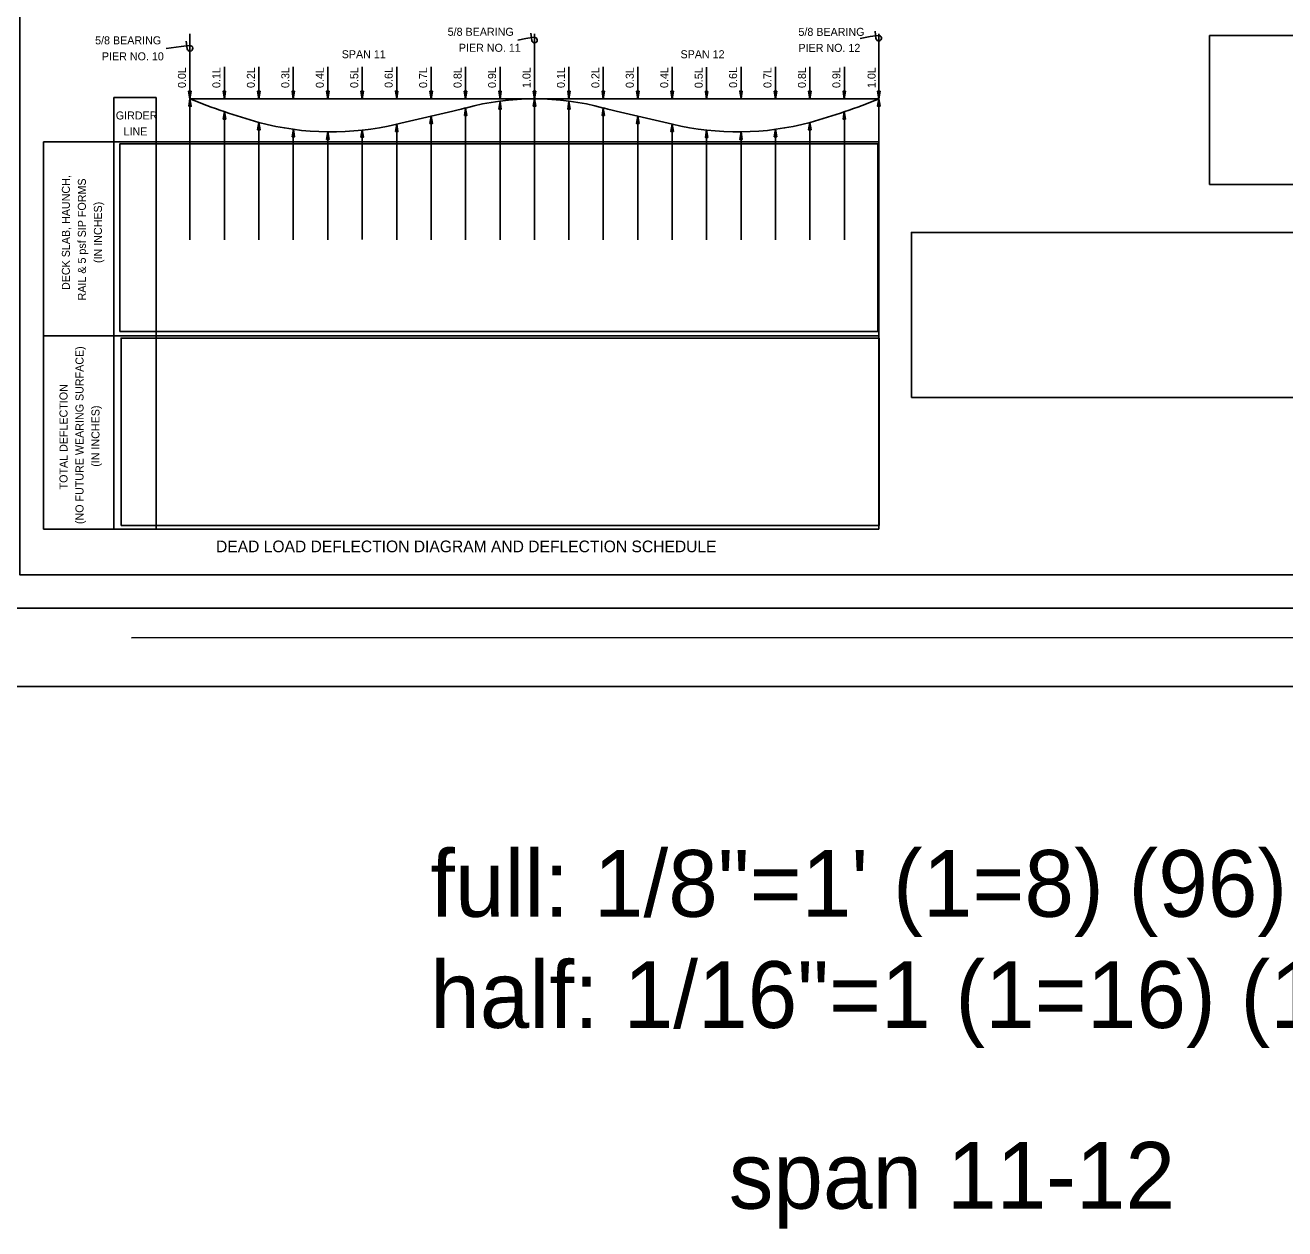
# Model space of a CAD drawing. Extents: x 4944 to 17449, y 3824 to 49087.
# Drawn here: x 7431 to 9244, y 35432 to 37164 of the extents above; entities that cross this region are included whole.
import ezdxf

# ---------------------------------------------------------------- set-up
doc = ezdxf.new("R2010")
doc.units = 0
for name, color, linetype in [('1', 7, 'Continuous'), ('37_S_TXT', 7, 'Continuous'), ('3A', 7, 'Continuous'), ('4', 7, 'Continuous'), ('6', 7, 'Continuous'), ('7', 7, 'Continuous'), ('BEAM', 7, 'Continuous'), ('DIM', 7, 'Continuous'), ('HATCH', 7, 'Continuous'), ('Level 14', 7, 'Continuous'), ('Level 25', 7, 'Continuous'), ('Level 34', 7, 'Continuous')]:
    doc.layers.add(name, color=color, linetype=linetype)

# ---------------------------------------------------------------- blocks, each defined once
blk = doc.blocks.new('DWG010')
at = {"layer": '1'}
for p, q in [((0, 0.047), (0.141, 0.047)), ((0.047, 0), (0.047, 0.125))]:
    blk.add_line(p, q, dxfattribs=at)
blk.add_arc((0, 0), 0.0469, 90, 0, dxfattribs=at)
blk = doc.blocks.new('ARROWH')
at = {"layer": '1'}
blk.add_lwpolyline([(0.123, -0.021), (0.123, 0.021), (-0.002, 0)], close=True, dxfattribs=at)

msp = doc.modelspace()

# ---------------------------------------------------------------- linework, layer by layer
at = {"layer": '37_S_TXT'}
msp.add_lwpolyline([(7079, 38515.9), (10535, 38515.9), (10535, 36211.9), (7079, 36211.9)], close=True, dxfattribs=at)
at = {"layer": '3A'}
for p, q in [((7668.1, 37151.1), (7668.1, 37057.9)), ((8163.9, 37151.1), (8163.9, 37057.9)), ((8659.4, 37151.1), (8659.4, 37057.9))]:
    msp.add_line(p, q, dxfattribs=at)
for points in [[(9135.4, 36934.3), (10068.7, 36934.3), (10068.7, 37148.9), (9135.4, 37148.9)], [(7567, 36723), (8657.9, 36723), (8657.9, 36992.8), (7567, 36992.8)], [(8706.4, 36627.8), (10414.2, 36627.8), (10414.2, 36865.5), (8706.4, 36865.5)], [(7569, 36443.7), (8659.8, 36443.7), (8659.8, 36713.5), (7569, 36713.5)]]:
    msp.add_lwpolyline(points, close=True, dxfattribs=at)
at = {"layer": '4'}
msp.add_line((7669.1, 36995.9), (8418.4, 36995.9), dxfattribs=at)
at = {"layer": '6'}
for p, q in [((8151.5, 37144.8), (8140, 37142.1)), ((8646.9, 37147.5), (8632.5, 37144.8)), ((7655.6, 37132.9), (7634, 37130.2)), ((7717.6, 37057.9), (7717.6, 37103.8)), ((7767.2, 37057.9), (7767.2, 37103.8)), ((7816.8, 37057.9), (7816.8, 37103.8)), ((7866.4, 37057.9), (7866.4, 37103.8)), ((7916, 37057.9), (7916, 37103.8)), ((7965.6, 37058.1), (7965.6, 37103.9)), ((8015.2, 37057.9), (8015.2, 37103.8)), ((8064.8, 37057.9), (8064.8, 37103.8)), ((8114.4, 37057.9), (8114.4, 37103.8)), ((8213.5, 37057.9), (8213.5, 37103.8)), ((8263, 37057.9), (8263, 37103.8)), ((8312.6, 37057.9), (8312.6, 37103.8)), ((8362.1, 37057.9), (8362.1, 37103.8)), ((8411.7, 37057.8), (8411.7, 37103.6)), ((8461.2, 37058.1), (8461.2, 37103.9)), ((8510.8, 37057.9), (8510.8, 37103.8)), ((8560.3, 37057.9), (8560.3, 37103.8)), ((8609.9, 37057.9), (8609.9, 37103.8)), ((7668.1, 36855.1), (7668.1, 37057.9)), ((7668.1, 37057.9), (7668.1, 37057.9)), ((7717.6, 37057.9), (7717.6, 37057.9)), ((7767.2, 37057.9), (7767.2, 37057.9)), ((7816.8, 37057.9), (7816.8, 37057.9)), ((7866.4, 37057.9), (7866.4, 37057.9)), ((7916, 37057.9), (7916, 37057.9)), ((7965.6, 37057.9), (7965.6, 37057.9)), ((8015.2, 37057.9), (8015.2, 37057.9)), ((8064.8, 37057.9), (8064.8, 37057.9)), ((8114.4, 37057.9), (8114.4, 37057.9)), ((8114.4, 36855.1), (8114.4, 37053.9)), ((8163.9, 36855.1), (8163.9, 37057.9)), ((8163.9, 37057.9), (8163.9, 37057.9)), ((8213.5, 37057.9), (8213.5, 37057.9)), ((8213.5, 36855.1), (8213.5, 37053.9)), ((8263, 37057.9), (8263, 37057.9)), ((8312.6, 37057.9), (8312.6, 37057.9)), ((8362.1, 37057.9), (8362.1, 37057.9)), ((8411.7, 37057.9), (8411.7, 37057.9)), ((8461.2, 37057.9), (8461.2, 37057.9)), ((8510.8, 37057.9), (8510.8, 37057.9)), ((8560.3, 37057.9), (8560.3, 37057.9)), ((8609.9, 37057.9), (8609.9, 37057.9)), ((8659.4, 36438.6), (8659.4, 37057.9)), ((8659.4, 37057.9), (8659.4, 37057.9)), ((7717.6, 36855.1), (7717.6, 37039.3)), ((8064.8, 36855.1), (8064.8, 37044.6)), ((8263, 36855.1), (8263, 37044.6)), ((8609.9, 36855.1), (8609.9, 37039.3)), ((7767.2, 36855.1), (7767.2, 37023.8)), ((7965.6, 36855.1), (7965.6, 37021.4)), ((8015.2, 36855.1), (8015.2, 37032.8)), ((8312.6, 36855.1), (8312.6, 37032.8)), ((8362.2, 36855.1), (8362.2, 37021.4)), ((8560.3, 36855.1), (8560.3, 37023.8)), ((7816.8, 36855.1), (7816.8, 37013.9)), ((7866.4, 36855.1), (7866.4, 37010.2)), ((7916, 36855.3), (7916, 37013.1)), ((8411.7, 36855.1), (8411.7, 37013)), ((8461.3, 36855.1), (8461.3, 37010.2)), ((8510.8, 36855.1), (8510.8, 37013.9))]:
    msp.add_line(p, q, dxfattribs=at)
at = {"layer": '7'}
for p, q in [((7668.1, 37057.9), (8163.9, 37057.9)), ((8163.9, 37057.9), (8659.4, 37057.9))]:
    msp.add_line(p, q, dxfattribs=at)
at = {"layer": 'BEAM'}
for centre, radius, start, end in [((8022.4, 37927.1), 938.7, 247.8233, 254.2284), ((8163.9, 36682.6), 375.3, 74.6834, 105.3166), ((8305.5, 37927.1), 938.7, 285.7716, 292.1767), ((6053.4, 45401.5), 8595.5, 282.85378, 283.53281), ((10274.5, 45401.5), 8595.5, 256.46719, 257.14622), ((7871.3, 37413.1), 402.9, 255.0329, 283.5345), ((8456.6, 37413.1), 402.9, 256.4655, 284.9671)]:
    msp.add_arc(centre, radius, start, end, dxfattribs=at)
at = {"layer": 'DIM'}
msp.add_lwpolyline([(7236.2, 38436.7), (10500.2, 38436.7), (10500.2, 36324.7), (7236.2, 36324.7)], close=True, dxfattribs=at)
at = {"layer": 'Level 14'}
msp.add_lwpolyline([(10447.4, 36372.7), (7423.4, 36372.7), (7423.4, 38388.7), (10447.4, 38388.7)], close=True, dxfattribs=at)
at = {"layer": 'Level 25'}
msp.add_line((7584.1, 36282.3), (10320.1, 36282.4), dxfattribs=at)
at = {"layer": 'Level 34'}
for p, q in [((7558.4, 36438.6), (7558.4, 37059.5)), ((7619.6, 37059.5), (7558.4, 37059.5)), ((7619.6, 36439.5), (7619.6, 37059.5)), ((7457.2, 36438.6), (7457.2, 36995.9)), ((8659.4, 36995.9), (7457.2, 36995.9)), ((7457.2, 36716.7), (8659.4, 36716.7)), ((7457.2, 36438.6), (8659.4, 36438.6))]:
    msp.add_line(p, q, dxfattribs=at)

# ---------------------------------------------------------------- block references
at = {"layer": '6'}
for name, p, xscale, yscale, rotation in [('DWG010', (8163.9, 37142.3), 85.92279574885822, -85.92279574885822, -172.86861111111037), ('DWG010', (8659.4, 37145), 85.92279574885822, -85.92279574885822, -172.8686111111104), ('DWG010', (7668.1, 37130.4), 85.92279574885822, -85.9227957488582, -172.86861111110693), ('ARROWH', (7668, 37058.1), 85.9227957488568, 85.9227957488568, 90), ('ARROWH', (7668.1, 37057.8), 85.92279574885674, 85.92279574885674, -90.00000000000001), ('ARROWH', (7717.6, 37058.1), 85.9227957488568, 85.9227957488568, 90), ('ARROWH', (7767.2, 37058.1), 85.9227957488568, 85.9227957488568, 90), ('ARROWH', (7816.8, 37058.1), 85.9227957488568, 85.9227957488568, 90), ('ARROWH', (7866.4, 37058.1), 85.9227957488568, 85.9227957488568, 90), ('ARROWH', (7916, 37058.1), 85.9227957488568, 85.9227957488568, 90), ('ARROWH', (7965.6, 37058.3), 85.9227957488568, 85.9227957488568, 90), ('ARROWH', (8015.2, 37058.1), 85.9227957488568, 85.9227957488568, 90), ('ARROWH', (8064.7, 37058.1), 85.9227957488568, 85.9227957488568, 90), ('ARROWH', (8114.3, 37058.1), 85.9227957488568, 85.9227957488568, 90), ('ARROWH', (8114.4, 37053.6), 85.92279574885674, 85.92279574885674, -90.00000000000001), ('ARROWH', (8163.9, 37058.1), 85.9227957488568, 85.9227957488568, 90), ('ARROWH', (8164, 37057.8), 85.92279574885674, 85.92279574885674, -90.00000000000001), ('ARROWH', (8213.5, 37058.1), 85.9227957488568, 85.9227957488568, 90), ('ARROWH', (8213.5, 37053.6), 85.92279574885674, -85.92279574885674, -90.00000000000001), ('ARROWH', (8263, 37058.1), 85.9227957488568, 85.9227957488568, 90), ('ARROWH', (8312.6, 37058.1), 85.9227957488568, 85.9227957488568, 90), ('ARROWH', (8362.1, 37058.1), 85.9227957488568, 85.9227957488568, 90), ('ARROWH', (8411.7, 37057.9), 85.9227957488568, 85.9227957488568, 90), ('ARROWH', (8461.2, 37058.3), 85.9227957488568, 85.9227957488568, 90), ('ARROWH', (8510.7, 37058.1), 85.9227957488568, 85.9227957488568, 90), ('ARROWH', (8560.3, 37058.1), 85.9227957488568, 85.9227957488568, 90), ('ARROWH', (8609.8, 37058.1), 85.9227957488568, 85.9227957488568, 90), ('ARROWH', (8659.4, 37058.1), 85.9227957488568, 85.9227957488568, 90), ('ARROWH', (8659.4, 37057.8), 85.92279574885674, -85.9227957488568, -90.00000000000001), ('ARROWH', (7717.7, 37039.2), 85.92279574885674, 85.92279574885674, -90.00000000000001), ('ARROWH', (8064.8, 37044.4), 85.92279574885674, 85.92279574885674, -90.00000000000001), ('ARROWH', (8263, 37044.4), 85.92279574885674, -85.92279574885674, -90.00000000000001), ('ARROWH', (8609.8, 37039.2), 85.92279574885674, -85.92279574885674, -90.00000000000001), ('ARROWH', (7767.3, 37023.7), 85.92279574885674, 85.92279574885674, -90.00000000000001), ('ARROWH', (7965.6, 37021.2), 85.92279574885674, 85.92279574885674, -90.00000000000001), ('ARROWH', (8015.2, 37032.7), 85.92279574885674, 85.92279574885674, -90.00000000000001), ('ARROWH', (8312.6, 37032.7), 85.92279574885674, -85.92279574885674, -90.00000000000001), ('ARROWH', (8362.1, 37021.2), 85.92279574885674, -85.92279574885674, -90.00000000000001), ('ARROWH', (8560.3, 37023.7), 85.92279574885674, -85.92279574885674, -90.00000000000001), ('ARROWH', (7816.9, 37013.8), 85.92279574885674, 85.92279574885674, -90.00000000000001), ('ARROWH', (7866.4, 37010), 85.92279574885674, 85.92279574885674, -90.00000000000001), ('ARROWH', (7916, 37013), 85.92279574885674, 85.92279574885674, -90.00000000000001), ('ARROWH', (8411.7, 37012.8), 85.92279574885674, -85.92279574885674, -90.00000000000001), ('ARROWH', (8461.2, 37010), 85.92279574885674, -85.92279574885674, -90.00000000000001), ('ARROWH', (8510.7, 37013.8), 85.92279574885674, -85.92279574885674, -90.00000000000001)]:
    msp.add_blockref(name, p, dxfattribs=dict(at, xscale=xscale, yscale=yscale, rotation=rotation))

# ---------------------------------------------------------------- texts
at = {"layer": '3A'}
for s, p in [('5/8 BEARING ', (7531.6, 37136.2)), ('5/8 BEARING ', (8039, 37148.5)), ('5/8 BEARING ', (8543.8, 37148.4)), ('SPAN 11', (7886.5, 37116.2)), ('PIER NO. 11', (8055.1, 37125.5)), ('SPAN 12', (8374.1, 37116.2)), ('PIER NO. 12', (8543.8, 37125.4)), ('PIER NO. 10', (7541.4, 37113.2)), ('GIRDER', (7561.4, 37028.1)), ('LINE', (7572.6, 37005.1))]:
    msp.add_text(s, height=11.52, dxfattribs=at).set_placement(p)
for s, p in [('0.0L', (7662.3, 37073.4)), ('0.1L', (7711.9, 37073.4)), ('0.2L', (7761.5, 37073.4)), ('0.3L', (7811.1, 37073.4)), ('0.4L', (7860.7, 37073.4)), ('0.5L', (7910.3, 37073.4)), ('0.6L', (7959.8, 37073.5)), ('0.7L', (8009.4, 37073.4)), ('0.8L', (8059, 37073.4)), ('0.9L', (8108.6, 37073.4)), ('1.0L', (8158.2, 37073.4)), ('0.1L', (8207.8, 37073.4)), ('0.2L', (8257.3, 37073.4)), ('0.3L', (8306.8, 37073.4)), ('0.4L', (8356.4, 37073.4)), ('0.5L', (8406, 37073.2)), ('0.6L', (8455.5, 37073.5)), ('0.7L', (8505, 37073.4)), ('0.8L', (8554.6, 37073.4)), ('0.9L', (8604.1, 37073.4)), ('1.0L', (8654.8, 37073.4)), ('DECK SLAB, HAUNCH,', (7495.3, 36782.7)), ('RAIL & 5 psf SIP FORMS', (7518.3, 36767.7)), ('(IN INCHES)', (7541.4, 36821.5)), ('(NO FUTURE WEARING SURFACE)', (7514.9, 36445.8)), ('TOTAL DEFLECTION', (7491.9, 36495.7)), ('(IN INCHES)', (7537.9, 36528.3))]:
    msp.add_text(s, height=11.52, rotation=90, dxfattribs=at).set_placement(p)
at = {"layer": 'BEAM'}
msp.add_text('DEAD LOAD DEFLECTION DIAGRAM AND DEFLECTION SCHEDULE', height=16.8, dxfattribs=at).set_placement((7705.6, 36405.3))
at = {"layer": 'HATCH'}
for s, p in [('full: 1/8"=1\' (1=8) (96)', (8013.9, 35880.7)), ('half: 1/16"=1 (1=16) (192)', (8013.9, 35720.7)), ('span 11-12', (8443.5, 35460.6))]:
    msp.add_text(s, height=96, dxfattribs=at).set_placement(p)

doc.saveas('drawing.dxf')
